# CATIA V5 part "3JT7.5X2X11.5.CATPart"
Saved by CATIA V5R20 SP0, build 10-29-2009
Part number: 3JT7.5X2X11.5
Revision: ANY
Definition: UNKNOWN
Nomenclature: 3JT7.5X2X11.5
Source: Unknown
Bounding box of the stored display mesh (mm): x -5.75 to 5.75, y -5.75 to 5.75, z -1 to 1
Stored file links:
  C:\Users\Utente\Desktop\IO LAVORO\3D X SITO CF\CUMSA\3D files PW\pw060830\pw060830_ejection\3JT7.5X2X11.5.CATPart
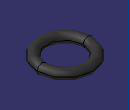
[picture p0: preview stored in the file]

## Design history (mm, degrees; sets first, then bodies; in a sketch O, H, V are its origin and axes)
Body1 "Revolución1" (main body)
  Solid1: solid without history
